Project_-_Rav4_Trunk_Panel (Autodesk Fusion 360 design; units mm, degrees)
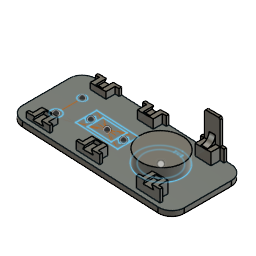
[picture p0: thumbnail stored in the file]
sketch "Sketch1" plane through (0, 0, 0) normal (0, 1, 0) x axis (1, 0, 0)
  line L1 (-61.3, -28.25) -> (61.3, -28.25)
  line L2 (-61.3, 28.25) -> (-61.3, -28.25)
  line L3 (61.3, 28.25) -> (-61.3, 28.25)
  line L4 (61.3, -28.25) -> (61.3, 28.25)
  line L5 (-61.3, 28.25) -> (61.3, -28.25)
  line L6 (61.3, 28.25) -> (-61.3, -28.25)
  line L7 (-12, 28.25) -> (0, 28.25)
  line L8 (-12, 26.65) -> (-12, 28.25)
  line L9 (0, 26.65) -> (-12, 26.65)
  line L10 (0, 28.25) -> (0, 26.65)
  line L11 (-36, 28.25) -> (-12, 28.25)
  line L12 (32, 28.25) -> (0, 28.25)
  line L13 (-48, 28.25) -> (-36, 28.25)
  line L14 (-48, 26.65) -> (-48, 28.25)
  line L15 (-36, 26.65) -> (-48, 26.65)
  line L16 (-36, 28.25) -> (-36, 26.65)
  line L17 (44, 28.25) -> (32, 28.25)
  line L18 (44, 26.65) -> (44, 28.25)
  line L19 (32, 26.65) -> (44, 26.65)
  line L20 (32, 28.25) -> (32, 26.65)
  line L21 (34, -24.95) -> (46, -24.95)
  line L22 (46, -23.35) -> (34, -23.35)
  line L23 (46, -24.95) -> (46, -23.35)
  line L24 (34, -23.35) -> (34, -24.95)
  line L25 (-12, -24.95) -> (-12, -23.35)
  line L26 (0, -23.35) -> (0, -24.95)
  line L27 (-12, -23.35) -> (0, -23.35)
  line L28 (0, -24.95) -> (-12, -24.95)
  line L29 (-38, -23.35) -> (-38, -24.95)
  line L30 (-38, -24.95) -> (-50, -24.95)
  line L31 (-50, -23.35) -> (-38, -23.35)
  line L32 (-50, -24.95) -> (-50, -23.35)
  point P6 (0, 0)
  point P1 (0, 0)
  point P7 (0, 28.25)
  point P4 (-61.3, 28.25)
  point P5 (61.3, 28.25)
  point P3 (-61.3, -28.25)
  point P8 (-12, 28.25)
  point P10 (0, 26.65)
  point P11 (-36, 28.25)
  point P12 (32, 28.25)
  point P13 (-48, 28.25)
  point P15 (-36, 26.65)
  point P16 (44, 28.25)
  point P18 (32, 26.65)
  point P19 (0, -23.35)
  point P23 (-12, -23.35)
  point P21 (0, -24.95)
  point P24 (-38, -23.35)
  point P25 (34, -23.35)
  point P26 (-50, -23.35)
  point P29 (-38, -24.95)
  point P28 (46, -23.35)
  point P27 (34, -24.95)
  horizontal L1
  perpendicular L1 L2
  parallel L1 L3
  parallel L2 L4
  coincident L5 P6
  coincident L6 P6
  coincident P1 P6
  horizontal L7
  vertical L8
  horizontal L9
  vertical L10
  midpoint L3 P7
  perpendicular L8 L11
  perpendicular L10 L12
  horizontal L13
  vertical L14
  horizontal L15
  vertical L16
  horizontal L17
  vertical L18
  horizontal L19
  vertical L20
  horizontal L27
  vertical L25
  horizontal L28
  vertical L26
  horizontal L31
  vertical L32
  horizontal L30
  vertical L29
  horizontal L22
  vertical L23
  horizontal L21
  vertical L24
  dimension "d1" distance P4 P5 = 122.6
  dimension "d2" distance P3 P4 = 56.5
  dimension "d4" distance P7 P8 = 12
  dimension "d5" distance P7 P10 = 1.6
  dimension "d6" distance P8 P11 = 24
  dimension "d7" distance P7 P12 = 32
  dimension "d8" distance P11 P13 = 12
  dimension "d9" distance P11 P15 = 1.6
  dimension "d10" distance P12 P16 = 12
  dimension "d11" distance P12 P18 = 1.6
  dimension "d12" distance P19 P23 = 12
  dimension "d13" distance P19 P21 = 1.6
  dimension "d14" distance P23 P24 = 26
  dimension "d15" distance P19 P25 = 34
  dimension "d16" distance P24 P26 = 12
  dimension "d17" distance P24 P29 = 1.6
  dimension "d18" distance P25 P28 = 12
  dimension "d19" distance P25 P27 = 1.6
work_plane "WorkPlane2" RotateAngle -3
sketch "Sketch8" plane through (-0.5226, -9.9726, 0) normal (0.0523, 0.9986, 0) x axis (0, 0, 1)
  line L1 (28.25, 62) -> (-28.25, 62)
  line L2 (28.25, -62) -> (28.25, 62)
  line L3 (-28.25, -62) -> (28.25, -62)
  line L4 (-28.25, 62) -> (-28.25, -62)
  line L5 (28.25, -62) -> (-28.25, 62)
  line L6 (-28.25, -62) -> (28.25, 62)
  point P6 (0, 0)
  point P1 (0, 0)
  point P4 (28.25, -62)
  point P5 (-28.25, -62)
  point P3 (28.25, 62)
  horizontal L1
  perpendicular L1 L2
  parallel L1 L3
  parallel L2 L4
  coincident L5 P6
  coincident L6 P6
  coincident P1 P6
  dimension "d22" distance P4 P5 = 56.5
  dimension "d23" distance P3 P4 = 124
extrude "Extrude1" new body sketch "Sketch1" profile of L7 L8 L9 L10 L13 L14 L15 L16 L17 L18 L19 L20 L21 L22 L23 L24 L25 L26 L27 L28 L29 L30 L31 L32 along normal blind 19
extrude "Extrude2" new body sketch "Sketch8" profile of L1 L2 L3 L4 along normal blind 3
move "Move1"
sketch "Sketch9" plane through (0, 0, 24.95) normal (0, 0, 1) x axis (1, 0, 0)
  line L1 (-38, 0) -> (-50, 0)
  line L2 (-38, 19) -> (-38, 0)
  line L3 (-50, 19) -> (-38, 19)
  line L4 (-50, 0) -> (-50, 19)
  line L5 (61.5382, -9.7888) -> (-62.3138, -3.7314)
  line L6 (-50, -4.3336) -> (-50, 0)
  line L7 (-38, -5) -> (-38, 0)
  line L8 (-12, -6.1922) -> (-12, 0)
  line L9 (0, -6.7791) -> (0, 0)
  line L10 (34, -8.4419) -> (34, 0)
  line L11 (46, -9.0288) -> (46, 0)
  line L12 (0, 0) -> (-12, 0)
  line L13 (34, 0) -> (46, 0)
  line L14 (-53, 0) -> (-50, 0)
  line L15 (-53, -4.1869) -> (-53, 0)
  line L16 (-35, 0) -> (-38, 0)
  line L17 (-35, -5.0673) -> (-35, 0)
  line L18 (31, 0) -> (34, 0)
  line L19 (31, -8.2952) -> (31, 0)
  line L20 (49, 0) -> (46, 0)
  line L21 (49, -9.1756) -> (49, 0)
  line L22 (3, 0) -> (0, 0)
  line L23 (3, -6.9258) -> (3, 0)
  line L24 (-15, 0) -> (-12, 0)
  line L25 (-15, -6.0454) -> (-15, 0)
  line L26 (0, 12.2) -> (0, 19)
  line L27 (3, 0) -> (0, 12.2)
  line L28 (-12, 12.2) -> (-12, 19)
  line L29 (-15, 0) -> (-12, 12.2)
  line L30 (-12, 12.2) -> (-12, 0)
  line L31 (0, 12.2) -> (0, 0)
  line L32 (-38, -4.3336) -> (-50, -4.3336)
  line L33 (-46.5, 0) -> (-50, 0)
  line L34 (-41.5, 0) -> (-38, 0)
  line L35 (-40, -3) -> (-44, -3)
  line L36 (-48, -3) -> (-44, -3)
  line L37 (-46.5, 0) -> (-48, -3)
  line L38 (-40, -3) -> (-41.5, 0)
  line L39 (-2, -3) -> (-3.5, 0)
  line L40 (-8.5, 0) -> (-10, -3)
  line L41 (-2, -3) -> (-6, -3)
  line L42 (-10, -3) -> (-6, -3)
  line L43 (44, -3) -> (42.5, 0)
  line L44 (44, -3) -> (40, -3)
  line L45 (37.5, 0) -> (36, -3)
  line L46 (36, -3) -> (40, -3)
  point P2 (-50, 0)
  point P8 (-50, 0)
  point P9 (-50, -4.3336)
  point P3 (-38, 0)
  point P10 (-38, 0)
  point P13 (-12, -6.1922)
  point P1 (0, 0)
  point P14 (0, 0)
  point P15 (0, -6.7791)
  point P17 (34, -8.4419)
  point P19 (46, -9.0288)
  point P25 (-53, -4.1869)
  point P27 (-35, -5.0673)
  point P23 (34, 0)
  point P28 (34, 0)
  point P30 (31, -8.2952)
  point P22 (46, 0)
  point P31 (46, 0)
  point P33 (49, -9.1756)
  point P34 (0, 0)
  point P36 (3, -6.9258)
  point P20 (-12, 0)
  point P37 (-12, 0)
  point P39 (-15, -6.0454)
  point P44 (0, 0)
  point P45 (-38, -4.3336)
  point P46 (-46.5, 0)
  point P47 (-41.5, 0)
  point P40 (0, 19)
  point P41 (0, 12.2)
  point P42 (-12, 19)
  point P43 (-12, 12.2)
  coincident P2 P8
  coincident L5 P9
  perpendicular L1 L6
  coincident P3 P10
  perpendicular L1 L7
  coincident L5 P13
  vertical L8
  coincident P1 P14
  coincident L5 P15
  vertical L9
  coincident L5 P17
  vertical L10
  coincident L5 P19
  parallel L10 L11
  perpendicular L6 L14
  coincident L5 P25
  perpendicular L14 L15
  perpendicular L7 L16
  coincident L5 P27
  perpendicular L16 L17
  coincident P23 P28
  perpendicular L10 L18
  coincident L5 P30
  perpendicular L13 L19
  coincident P22 P31
  perpendicular L11 L20
  coincident L5 P33
  perpendicular L20 L21
  coincident P1 P34
  perpendicular L9 L22
  coincident L5 P36
  perpendicular L22 L23
  coincident P20 P37
  perpendicular L8 L24
  coincident L5 P39
  perpendicular L24 L25
  vertical L26
  vertical L28
  perpendicular L12 L30
  coincident P1 P44
  perpendicular L22 L31
  coincident L7 P45
  perpendicular L7 L32
  coincident L1 P46
  coincident L1 P47
  parallel L35 L36
  parallel L41 L42
  parallel L44 L46
  dimension "d30" distance P40 P41 = 6.8
  dimension "d31" distance P42 P43 = 6.8
extrude "Extrude5" new body sketch "Sketch9" profile of L1 L35 L36 L37 L38 against normal blind 8
copy_paste_bodies "CopyPasteBodies2"
move "Move5"
copy_paste_bodies "CopyPasteBodies3"
move "Move6"
copy_paste_bodies "CopyPasteBodies4"
move "Move7"
move "Move8"
move "Move9"
extrude "Extrude6" new body sketch "Sketch9" profile of L5 L6 L7 L8 L9 L10 L11 L14 L15 L16 L17 L18 L19 L20 L21 L22 L23 L24 L25 L27 L29 L30 L31 against normal blind 1.6
extrude "Extrude7" add sketch "Sketch9" profile of L1 L5 L6 L7 L8 L9 L10 L11 L12 L13 L35 L36 L37 L38 L39 L40 L41 L42 L43 L44 L45 L46 against normal blind 9
extrude "Extrude8" cut sketch "Sketch9" profile of L1 L12 L13 L35 L36 L37 L38 L39 L40 L41 L42 L43 L44 L45 L46 against normal blind 8
extrude "Extrude9" cut sketch "Sketch9" profile of L22 L24 L27 L29 L30 L31 against normal blind 4
sketch "Sketch12" plane through (0, 0, -28.25) normal (0, 0, -1) x axis (-1, 0, 0)
  line L1 (12, 0) -> (0, 0)
  line L2 (12, 19) -> (12, 0)
  line L3 (0, 19) -> (12, 19)
  line L4 (0, 0) -> (0, 19)
  line L5 (-29, 0) -> (-32, 0)
  line L6 (-61.5382, -9.7888) -> (62.3138, -3.7314)
  line L7 (-34, -3) -> (-42, -3)
  line L8 (-35.5, 0) -> (-34, -3)
  line L9 (-40.5, 0) -> (-35.5, 0)
  line L10 (-42, -3) -> (-40.5, 0)
  line L11 (10, -3) -> (2, -3)
  line L12 (8.5, 0) -> (10, -3)
  line L13 (3.5, 0) -> (8.5, 0)
  line L14 (2, -3) -> (3.5, 0)
  line L15 (46, -3) -> (38, -3)
  line L16 (44.5, 0) -> (46, -3)
  line L17 (39.5, 0) -> (44.5, 0)
  line L18 (38, -3) -> (39.5, 0)
  line L19 (-47, 0) -> (-44, 0)
  line L20 (-47, -9.0777) -> (-47, 0)
  line L21 (-29, -8.1974) -> (-29, 0)
  line L22 (-3, 0) -> (0, 0)
  line L23 (-3, -6.9258) -> (-3, 0)
  line L24 (15, 0) -> (12, 0)
  line L25 (15, -6.0454) -> (15, 0)
  line L26 (33, 0) -> (36, 0)
  line L27 (33, -5.1651) -> (33, 0)
  line L28 (51, 0) -> (48, 0)
  line L29 (51, -4.2847) -> (51, 0)
  line L30 (48, -4.4315) -> (48, 0)
  line L31 (36, -5.0184) -> (36, 0)
  line L32 (39.5, 0) -> (36, 0)
  line L33 (48, 0) -> (44.5, 0)
  line L34 (12, -6.1922) -> (12, 0)
  line L35 (0, -6.7791) -> (0, 0)
  line L36 (-32, -8.3441) -> (-32, 0)
  line L37 (-44, -8.931) -> (-44, 0)
  line L38 (-32, 0) -> (-35.5, 0)
  line L39 (-44, 0) -> (-40.5, 0)
  line L40 (0, 12.2) -> (0, 19)
  line L41 (12, 12.2) -> (12, 19)
  line L42 (0, 0) -> (0, 12.2)
  line L43 (12, 0) -> (12, 12.2)
  line L44 (6, 5.4) -> (6, 0)
  line L45 (8.3, 5.4) -> (6, 5.4)
  line L46 (3.7, 5.4) -> (6, 5.4)
  line L47 (3.7, 10.4) -> (3.7, 5.4)
  line L48 (8.3, 10.4) -> (3.7, 10.4)
  line L49 (8.3, 5.4) -> (8.3, 10.4)
  line L50 (-1.5, 0) -> (0, 12.2)
  line L51 (13.5, 0) -> (12, 12.2)
  point P24 (-47, -9.0777)
  point P25 (-29, -8.1974)
  point P2 (0, 0)
  point P26 (0, 0)
  point P28 (-3, -6.9258)
  point P3 (12, 0)
  point P29 (12, 0)
  point P31 (15, -6.0454)
  point P34 (33, -5.1651)
  point P37 (51, -4.2847)
  point P38 (48, -4.4315)
  point P39 (36, -5.0184)
  point P21 (39.5, 0)
  point P40 (39.5, 0)
  point P20 (44.5, 0)
  point P41 (44.5, 0)
  point P42 (12, -6.1922)
  point P43 (0, -6.7791)
  point P44 (-32, -8.3441)
  point P45 (-44, -8.931)
  point P12 (-35.5, 0)
  point P46 (-35.5, 0)
  point P13 (-40.5, 0)
  point P47 (-40.5, 0)
  point P5 (0, 19)
  point P48 (0, 19)
  point P4 (12, 19)
  point P50 (12, 19)
  point P52 (0, 0)
  point P53 (6, 0)
  point P59 (-1.5, 0)
  point P60 (13.5, 0)
  point P6 (-32, 0)
  point P7 (-29, 0)
  point P22 (-44, 0)
  point P23 (-47, 0)
  point P32 (36, 0)
  point P33 (33, 0)
  point P49 (0, 12.2)
  point P51 (12, 12.2)
  point P54 (6, 5.4)
  point P55 (8.3, 5.4)
  point P56 (3.7, 5.4)
  point P57 (3.7, 10.4)
  horizontal L5
  parallel L9 L19
  coincident L6 P24
  perpendicular L9 L20
  coincident L6 P25
  perpendicular L5 L21
  coincident P2 P26
  perpendicular L4 L22
  coincident L6 P28
  perpendicular L1 L23
  coincident P3 P29
  perpendicular L2 L24
  coincident L6 P31
  perpendicular L24 L25
  perpendicular L25 L26
  coincident L6 P34
  perpendicular L24 L27
  perpendicular L27 L28
  coincident L6 P37
  perpendicular L28 L29
  coincident L6 P38
  perpendicular L28 L30
  coincident L6 P39
  perpendicular L26 L31
  coincident P21 P40
  perpendicular L31 L32
  coincident P20 P41
  perpendicular L30 L33
  coincident L6 P42
  perpendicular L24 L34
  coincident L6 P43
  perpendicular L22 L35
  coincident L6 P44
  perpendicular L5 L36
  coincident L6 P45
  perpendicular L19 L37
  coincident P12 P46
  perpendicular L36 L38
  coincident P13 P47
  perpendicular L37 L39
  coincident P5 P48
  perpendicular L3 L40
  coincident P4 P50
  perpendicular L3 L41
  coincident P2 P52
  midpoint L13 P53
  perpendicular L13 L44
  perpendicular L44 L45
  perpendicular L44 L46
  perpendicular L46 L47
  perpendicular L47 L48
  perpendicular L45 L49
  midpoint L22 P59
  midpoint L24 P60
  dimension "d44" distance P6 P7 = 3
  dimension "d45" distance P22 P23 = 3
  dimension "d46" distance P32 P33 = 3
  dimension "d49" distance P48 P49 = 6.8
  dimension "d50" distance P50 P51 = 6.8
  dimension "d59" distance P53 P54 = 5.4
  dimension "d60" distance P54 P55 = 2.3
  dimension "d61" distance P54 P56 = 2.3
  dimension "d62" distance P56 P57 = 5
extrude "Extrude10" add sketch "Sketch12" profile of L5 L6 L19 L20 L21 L22 L23 L24 L25 L26 L27 L28 L29 L30 L31 L34 L35 L36 L37 against normal blind 1.6
split "Split1"
extrude "Extrude11" add sketch "Sketch12" profile of L1 L6 L7 L8 L9 L10 L11 L12 L13 L14 L15 L16 L17 L18 L30 L31 L32 L33 L34 L35 L36 L37 L38 L39 against normal blind 9
extrude "Extrude12" cut sketch "Sketch12" profile of L1 L7 L8 L9 L10 L11 L12 L13 L14 L15 L16 L17 L18 against normal blind 8
combine "Combine1"
combine "Combine2"
combine "Combine3"
combine "Combine4"
combine "Combine5"
combine "Combine6"
extrude "Extrude13" add sketch "Sketch9" profile of L22 L24 L27 L29 L30 L31 against normal blind 1.6
extrude "Extrude14" add sketch "Sketch12" profile of L2 L4 L22 L24 L42 L43 against normal blind 1.6
extrude "Extrude15" new body sketch "Sketch12" profile of L45 L46 L47 L48 L49 along normal blind 1.6
sketch "Sketch13" plane through (-3.7, 0, 0) normal (1, 0, 0) x axis (0, 0, -1)
  line L1 (28.25, 5.4) -> (28.25, 10.4)
  line L2 (29.85, 5.4) -> (28.25, 5.4)
  line L3 (29.85, 10.4) -> (29.85, 5.4)
  line L4 (28.25, 10.4) -> (29.85, 10.4)
  line L5 (29.85, 6) -> (28.25, 10.4)
  point P2 (28.25, 10.4)
  point P6 (28.25, 10.4)
  point P7 (29.85, 6)
  coincident P2 P6
  coincident L3 P7
extrude "Extrude16" cut sketch "Sketch13" profile of L3 L4 L5 against normal blind 13.5
copy_paste_bodies "CopyPasteBodies5"
move "Move10"
remove_body "RemoveBody1"
remove_body "RemoveBody2"
remove_body "RemoveBody3"
remove_body "RemoveBody4"
combine "Combine7"
combine "Combine8"
chamfer "Chamfer1" distance 1
offset_faces "OffsetFaces1" distance -0.08
offset_faces "OffsetFaces2" distance -0.08
offset_faces "OffsetFaces3" distance -0.08
chamfer "Chamfer2" distance 0.8
fillet "Fillet1" radius 10
split "Split2"
move "Move12"
move_face "MoveFace1"
move_face "MoveFace2"
extrude "Extrude17" add of existing geometry blind 1
extrude "Extrude18" add of existing geometry blind 0.4
extrude "Extrude19" add of existing geometry blind 0.4
extrude "Extrude20" add of existing geometry blind 0.4
offset_faces "OffsetFaces4" distance 0.08
work_plane "WorkPlane3" RotateAngle 90
sketch "Sketch14" plane through (-8.4106, 0, 0) normal (1, 0, 0) x axis (0, 0, -1)
  line L1 (26.25, 0) -> (20.25, 0)
  line L2 (26.25, 0) -> (26.25, 12.2)
  arc A1 centre (20.1492, 6.1) radius 6.1008 clockwise from (26.25, 6.1) to (20.25, 0)
  point P7 (26.25, 6.1)
  point P2 (20.25, 0)
  point P6 (20.25, 0)
  tangent L2 A1
  midpoint L2 P7
  coincident P2 P6
extrude "Extrude21" new body sketch "Sketch14" along normal blind 4.821
copy_paste_bodies "CopyPasteBodies7"
move "Move13"
combine "Combine9"
combine "Combine10"
extrude "Extrude22" add sketch "Sketch12" profile of L4 L22 L42 L50 against normal blind 2
extrude "Extrude23" cut of existing geometry blind -0.08
combine "Combine11"
combine "Combine12"
move_face "MoveFace3"
move_face "MoveFace4"
move_face "MoveFace5"
move_face "MoveFace6"
move "Move14"
sketch "Sketch16" plane through (-0.3308, -6.7629, 0) normal (0.0488, 0.9988, 0) x axis (0, 0, -1)
  line L1 (17.75, -61.1429) -> (-18.25, -61.1429)
  line L2 (27.75, -47.3873) -> (27.75, -51.1429)
  line L3 (25.75, -47.3873) -> (27.75, -47.3873)
  line L4 (25.75, -44.3837) -> (25.75, -47.3873)
  line L5 (18.75, -44.3837) -> (25.75, -44.3837)
  line L6 (18.75, -32.3694) -> (18.75, -44.3837)
  line L7 (25.75, -32.3694) -> (18.75, -32.3694)
  line L8 (25.75, -29.3658) -> (25.75, -32.3694)
  line L9 (27.75, -29.3658) -> (25.75, -29.3658)
  line L10 (27.75, -3.3347) -> (27.75, -29.3658)
  line L11 (25.75, -3.3347) -> (27.75, -3.3347)
  line L12 (25.75, -0.3312) -> (25.75, -3.3347)
  line L13 (18.75, -0.3312) -> (25.75, -0.3312)
  line L14 (18.75, 11.6832) -> (18.75, -0.3312)
  line L15 (25.75, 11.6832) -> (18.75, 11.6832)
  line L16 (25.75, 14.6868) -> (25.75, 11.6832)
  line L17 (27.75, 14.6868) -> (25.75, 14.6868)
  line L18 (27.75, 32.7083) -> (27.75, 14.6868)
  line L19 (25.75, 32.7083) -> (27.75, 32.7083)
  line L20 (25.75, 35.7119) -> (25.75, 32.7083)
  line L21 (18.75, 35.7119) -> (25.75, 35.7119)
  line L22 (18.75, 47.7262) -> (18.75, 35.7119)
  line L23 (25.75, 47.7262) -> (18.75, 47.7262)
  line L24 (25.75, 50.7298) -> (25.75, 47.7262)
  line L25 (27.75, 50.7298) -> (25.75, 50.7298)
  line L26 (27.75, 52.2571) -> (27.75, 50.7298)
  line L27 (-18.25, 62.2571) -> (17.75, 62.2571)
  line L28 (-28.25, -51.1429) -> (-28.25, 52.2571)
  line L29 (-22.95, -31.3682) -> (-24.95, -31.3682)
  line L30 (-22.95, -34.3718) -> (-22.95, -31.3682)
  line L31 (-15.95, -34.3718) -> (-22.95, -34.3718)
  line L32 (-15.95, -46.3861) -> (-15.95, -34.3718)
  line L33 (-22.95, -46.3861) -> (-15.95, -46.3861)
  line L34 (-22.95, -49.3897) -> (-22.95, -46.3861)
  line L35 (-24.95, -49.3897) -> (-22.95, -49.3897)
  line L36 (-24.95, -31.3682) -> (-24.95, -49.3897)
  line L37 (-22.95, 52.7322) -> (-24.95, 52.7322)
  line L38 (-22.95, 49.7286) -> (-22.95, 52.7322)
  line L39 (-15.95, 49.7286) -> (-22.95, 49.7286)
  line L40 (-15.95, 37.7143) -> (-15.95, 49.7286)
  line L41 (-22.95, 37.7143) -> (-15.95, 37.7143)
  line L42 (-22.95, 34.7107) -> (-22.95, 37.7143)
  line L43 (-24.95, 34.7107) -> (-22.95, 34.7107)
  line L44 (-24.95, 52.7322) -> (-24.95, 34.7107)
  line L45 (-24.95, -3.3347) -> (-22.95, -3.3347)
  line L46 (-24.95, 14.6868) -> (-24.95, -3.3347)
  line L47 (-22.95, 14.6868) -> (-24.95, 14.6868)
  line L48 (-22.95, 11.6832) -> (-22.95, 14.6868)
  line L49 (-15.95, 11.6832) -> (-22.95, 11.6832)
  line L50 (-15.95, -0.3312) -> (-15.95, 11.6832)
  line L51 (-22.95, -0.3312) -> (-15.95, -0.3312)
  line L52 (-22.95, -3.3347) -> (-22.95, -0.3312)
  line L53 (12.5211, -27.6575) -> (14.0411, -27.6575)
  line L54 (14.0411, -22.3425) -> (12.5211, -22.3425)
  line L55 (14.0411, -27.6575) -> (12.5211, -27.6575)
  line L56 (14.0411, -22.3425) -> (14.0411, -27.6575)
  line L57 (-6, 25.1) -> (6, 25.1)
  line L58 (-6, 6.9) -> (-6, 25.1)
  line L59 (6, 6.9) -> (-6, 6.9)
  line L60 (6, 25.1) -> (6, 6.9)
  line L61 (-6, 6.9) -> (6, 25.1)
  line L62 (6, 6.9) -> (-6, 25.1)
  line L63 (0, 28.5) -> (0, 16)
  line L64 (0, 3.5) -> (0, 16)
  line L65 (8, 32) -> (-8, 32)
  line L66 (8, 0) -> (8, 32)
  line L67 (-8, 0) -> (8, 0)
  line L68 (-8, 32) -> (-8, 0)
  line L69 (8, 0) -> (-8, 32)
  line L70 (-8, 0) -> (8, 32)
  line L71 (10, 45) -> (0, 45)
  line L72 (-10, 45) -> (0, 45)
  line L73 (3.3486, 3.5) -> (1.6743, 0.6)
  line L74 (1.6743, 6.4) -> (3.3486, 3.5)
  line L75 (-1.6743, 6.4) -> (1.6743, 6.4)
  line L76 (-3.3486, 3.5) -> (-1.6743, 6.4)
  line L77 (-1.6743, 0.6) -> (-3.3486, 3.5)
  line L78 (1.6743, 0.6) -> (-1.6743, 0.6)
  line L79 (3.3486, 28.5) -> (1.6743, 25.6)
  line L80 (1.6743, 31.4) -> (3.3486, 28.5)
  line L81 (-1.6743, 31.4) -> (1.6743, 31.4)
  line L82 (-3.3486, 28.5) -> (-1.6743, 31.4)
  line L83 (-1.6743, 25.6) -> (-3.3486, 28.5)
  line L84 (1.6743, 25.6) -> (-1.6743, 25.6)
  arc A1 centre (-18.25, -51.1429) radius 10 clockwise from (-18.25, -61.1429) to (-28.25, -51.1429)
  arc A2 centre (17.75, -51.1429) radius 10 clockwise from (27.75, -51.1429) to (17.75, -61.1429)
  arc A3 centre (17.75, 52.2571) radius 10 clockwise from (17.75, 62.2571) to (27.75, 52.2571)
  arc A4 centre (-18.25, 52.2571) radius 10 clockwise from (-28.25, 52.2571) to (-18.25, 62.2571)
  circle C1 centre (0, -25) radius 12.8
  circle C2 centre (0, -25) radius 16.5
  circle C3 centre (0, 28.5) radius 1.8
  circle C4 centre (0, 3.5) radius 1.8
  circle C5 centre (10, 45) radius 2.9
  circle C6 centre (-10, 45) radius 3.8
  point P64 (12.5211, -27.6575)
  point P65 (12.5211, -22.3425)
  point P72 (0, 16)
  point P73 (0, 16)
  point P75 (0, 16)
  point P74 (0, 28.5)
  point P77 (0, 28.5)
  point P76 (0, 3.5)
  point P78 (0, 3.5)
  point P83 (0, 16)
  point P85 (10, 45)
  point P87 (10, 45)
  point P86 (-10, 45)
  point P88 (-10, 45)
  point P95 (0, 3.5)
  point P102 (0, 28.5)
  point P66 (14.0411, -27.6575)
  point P70 (-6, 6.9)
  point P71 (6, 6.9)
  point P69 (-6, 25.1)
  point P67 (14.0411, -22.3425)
  concentric C1 C2
  horizontal L53
  parallel L53 L54
  coincident C1 P64
  coincident C1 P65
  perpendicular L54 L56
  horizontal L57
  perpendicular L57 L58
  parallel L57 L59
  parallel L58 L60
  coincident L61 P72
  coincident L62 P72
  coincident P72 P73
  parallel L60 L63
  coincident P72 P75
  perpendicular L59 L64
  coincident P74 P77
  coincident P76 P78
  horizontal L65
  perpendicular L65 L66
  parallel L65 L67
  parallel L66 L68
  coincident L69 P83
  coincident L70 P83
  coincident P72 P83
  horizontal L71
  perpendicular L40 L72
  coincident P85 P87
  coincident P86 P88
  coincident P76 P95
  coincident P77 P102
  dimension "d90" diameter C1 = 25.6
  dimension "d91" diameter C2 = 33
  dimension "d94" distance P64 P66 = 1.52
  dimension "d101" distance P70 P71 = 12
  dimension "d102" distance P69 P70 = 18.2
  dimension "d103" distance P73 P74 = 12.5
  dimension "d104" distance P75 P76 = 12.5
  dimension "d105" diameter C3 = 3.6
  dimension "d106" diameter C4 = 3.6
  dimension "d107" diameter C5 = 5.8
  dimension "d108" diameter C6 = 7.6
  dimension "d118" distance P65 P67 = 1.52
  dimension "d119" distance P95 L78 = 2.9
  dimension "d120" distance P102 L84 = 2.9
extrude "Extrude24" new body sketch "Sketch16" profile of C1 C2 L53 L54 L55 L56 against normal blind 2
extrude "Extrude25" add sketch "Sketch16" profile of C1 L53 L54 L55 L56 against normal blind 4
extrude "Extrude26" add sketch "Sketch16" profile of C1 C2 L53 L54 L55 L56 along normal blind 10
extrude "Extrude27" new body sketch "Sketch16" profile of L57 L58 L59 L60 C3 C4 against normal blind 4
extrude "Extrude28" add sketch "Sketch16" profile of L57 L58 L59 L60 C3 C4 L65 L66 L67 L68 along normal blind 10
extrude "Extrude29" new body sketch "Sketch16" profile of C5 C6 against normal blind 4
extrude "Extrude30" add sketch "Sketch16" profile of C5 C6 along normal blind 10
extrude "Extrude31" add sketch "Sketch16" profile of C3 C4 L73 L74 L75 L76 L77 L78 L79 L80 L81 L82 L83 L84 against normal blind 3
extrude "Extrude32" cut of existing geometry blind -1
copy_paste_bodies "CopyPasteBodies8"
move "Move15"
copy_paste_bodies "CopyPasteBodies9"
move "Move16"
combine "Combine13"
sketch "Sketch17" plane through (-0.3308, -6.7629, 0) normal (0.0488, 0.9988, 0) x axis (0, 0, -1)
  line L1 (98.3257, 6.4) -> (96.6514, 3.5)
  line L2 (101.6743, 6.4) -> (98.3257, 6.4)
  line L3 (103.3486, 3.5) -> (101.6743, 6.4)
  line L4 (101.6743, 0.6) -> (103.3486, 3.5)
  line L5 (98.3257, 0.6) -> (101.6743, 0.6)
  line L6 (96.6514, 3.5) -> (98.3257, 0.6)
  line L7 (98.3257, 31.4) -> (96.6514, 28.5)
  line L8 (101.6743, 31.4) -> (98.3257, 31.4)
  line L9 (103.3486, 28.5) -> (101.6743, 31.4)
  line L10 (101.6743, 25.6) -> (103.3486, 28.5)
  line L11 (98.3257, 25.6) -> (101.6743, 25.6)
  line L12 (96.6514, 28.5) -> (98.3257, 25.6)
  line L13 (106, 25.1) -> (94, 25.1)
  line L14 (106, 6.9) -> (106, 25.1)
  line L15 (94, 6.9) -> (106, 6.9)
  line L16 (94, 25.1) -> (94, 6.9)
  line L17 (117.75, -61.1429) -> (81.75, -61.1429)
  line L18 (127.75, -47.3873) -> (127.75, -51.1429)
  line L19 (125.75, -47.3873) -> (127.75, -47.3873)
  line L20 (125.75, -44.3837) -> (125.75, -47.3873)
  line L21 (118.75, -44.3837) -> (125.75, -44.3837)
  line L22 (118.75, -32.3694) -> (118.75, -44.3837)
  line L23 (125.75, -32.3694) -> (118.75, -32.3694)
  line L24 (125.75, -29.3658) -> (125.75, -32.3694)
  line L25 (127.75, -29.3658) -> (125.75, -29.3658)
  line L26 (127.75, -3.3347) -> (127.75, -29.3658)
  line L27 (125.75, -3.3347) -> (127.75, -3.3347)
  line L28 (125.75, -0.3312) -> (125.75, -3.3347)
  line L29 (118.75, -0.3312) -> (125.75, -0.3312)
  line L30 (118.75, 11.6832) -> (118.75, -0.3312)
  line L31 (125.75, 11.6832) -> (118.75, 11.6832)
  line L32 (125.75, 14.6868) -> (125.75, 11.6832)
  line L33 (127.75, 14.6868) -> (125.75, 14.6868)
  line L34 (127.75, 32.7083) -> (127.75, 14.6868)
  line L35 (125.75, 32.7083) -> (127.75, 32.7083)
  line L36 (125.75, 35.7119) -> (125.75, 32.7083)
  line L37 (118.75, 35.7119) -> (125.75, 35.7119)
  line L38 (118.75, 47.7262) -> (118.75, 35.7119)
  line L39 (125.75, 47.7262) -> (118.75, 47.7262)
  line L40 (125.75, 50.7298) -> (125.75, 47.7262)
  line L41 (127.75, 50.7298) -> (125.75, 50.7298)
  line L42 (127.75, 52.2571) -> (127.75, 50.7298)
  line L43 (81.75, 62.2571) -> (117.75, 62.2571)
  line L44 (71.75, -51.1429) -> (71.75, 52.2571)
  line L45 (77.05, -31.3682) -> (75.05, -31.3682)
  line L46 (77.05, -34.3718) -> (77.05, -31.3682)
  line L47 (84.05, -34.3718) -> (77.05, -34.3718)
  line L48 (84.05, -46.3861) -> (84.05, -34.3718)
  line L49 (77.05, -46.3861) -> (84.05, -46.3861)
  line L50 (77.05, -49.3897) -> (77.05, -46.3861)
  line L51 (75.05, -49.3897) -> (77.05, -49.3897)
  line L52 (75.05, -31.3682) -> (75.05, -49.3897)
  line L53 (77.05, 52.7322) -> (75.05, 52.7322)
  line L54 (77.05, 49.7286) -> (77.05, 52.7322)
  line L55 (84.05, 49.7286) -> (77.05, 49.7286)
  line L56 (84.05, 37.7143) -> (84.05, 49.7286)
  line L57 (77.05, 37.7143) -> (84.05, 37.7143)
  line L58 (77.05, 34.7107) -> (77.05, 37.7143)
  line L59 (75.05, 34.7107) -> (77.05, 34.7107)
  line L60 (75.05, 52.7322) -> (75.05, 34.7107)
  line L61 (75.05, -3.3347) -> (77.05, -3.3347)
  line L62 (75.05, 14.6868) -> (75.05, -3.3347)
  line L63 (77.05, 14.6868) -> (75.05, 14.6868)
  line L64 (77.05, 11.6832) -> (77.05, 14.6868)
  line L65 (84.05, 11.6832) -> (77.05, 11.6832)
  line L66 (84.05, -0.3312) -> (84.05, 11.6832)
  line L67 (77.05, -0.3312) -> (84.05, -0.3312)
  line L68 (77.05, -3.3347) -> (77.05, -0.3312)
  circle C1 centre (100, -25) radius 16.5
  circle C2 centre (110, 45) radius 2.9
  circle C3 centre (90, 45) radius 3.8
  arc A1 centre (81.75, -51.1429) radius 10 clockwise from (81.75, -61.1429) to (71.75, -51.1429)
  arc A2 centre (117.75, -51.1429) radius 10 clockwise from (127.75, -51.1429) to (117.75, -61.1429)
  arc A3 centre (117.75, 52.2571) radius 10 clockwise from (117.75, 62.2571) to (127.75, 52.2571)
  arc A4 centre (81.75, 52.2571) radius 10 clockwise from (71.75, 52.2571) to (81.75, 62.2571)
  circle C4 centre (110, 45) radius 6
  concentric C2 C4
extrude "Extrude33" cut sketch "Sketch17" profile of C2 C4 against normal blind 2
copy_paste_bodies "CopyPasteBodies10"
move "Move17"
combine "Combine14"
extrude "Extrude3" new body sketch "Sketch9" profile of L1 L5 L6 L7 L8 L9 L10 L11 L12 L13 against normal blind 10
extrude "Extrude4" new body sketch "Sketch9" profile of L5 L6 L7 L8 L9 L10 L11 L14 L15 L16 L17 L18 L19 L20 L21 L22 L23 L24 L25 L27 L29 L30 L31 against normal blind 1.6
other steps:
base_feature "Base Feature2"
base_feature "Base Feature3"
base_feature "Base Feature4"
base_feature "Base Feature5"
base_feature "Base Feature7"
base_feature "Base Feature8"
base_feature "Base Feature9"
base_feature "Base Feature10"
